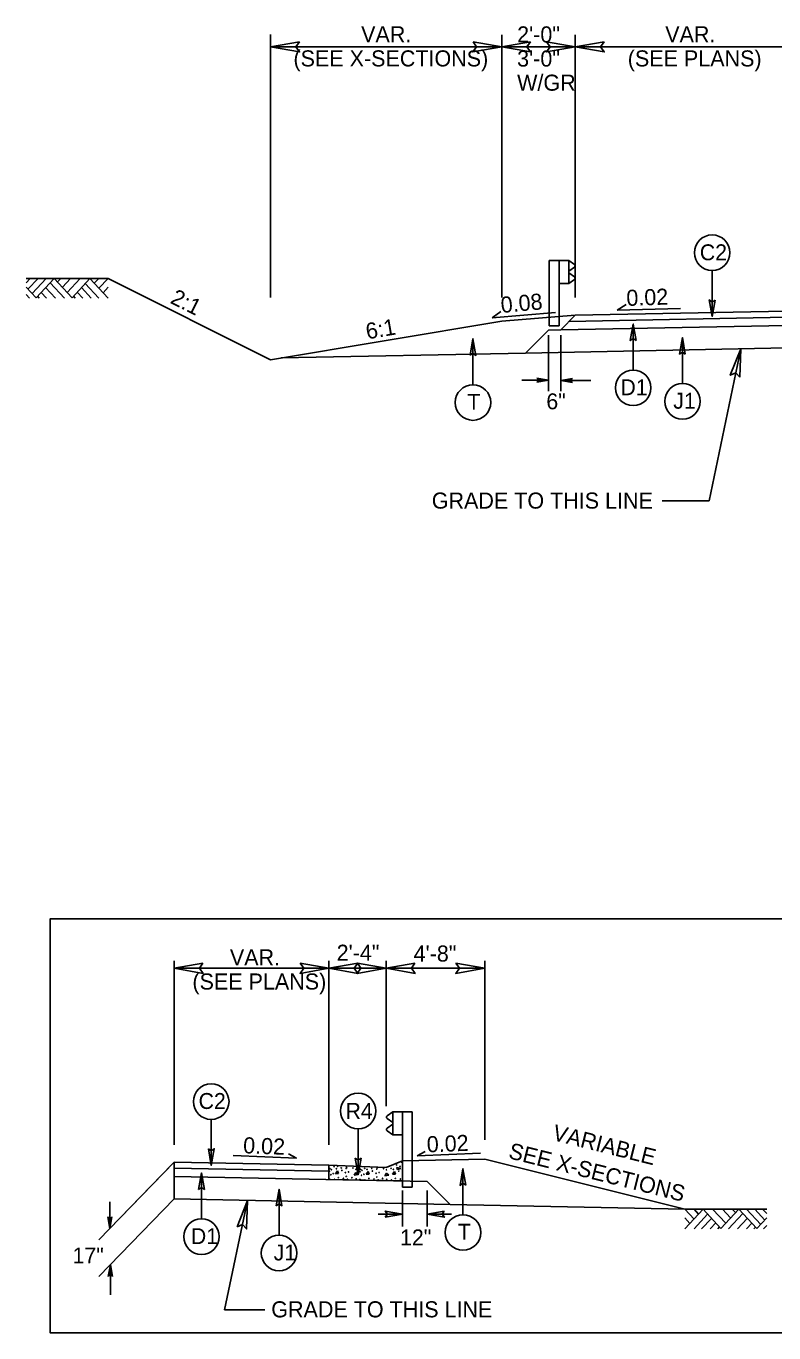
# Model space of a CAD drawing. Extents: x 1901582 to 1902252, y 193723 to 194156.
# Drawn here: x 1901984 to 1902014.5, y 193874.8 to 193928 of the extents above; entities that cross this region are included whole.
import ezdxf

# ---------------------------------------------------------------- set-up
doc = ezdxf.new("R2010")
doc.units = 0
for name, color, linetype in [('Default', 7, 'Continuous'), ('Old_Level_1', 7, 'Continuous'), ('Old_Level_11', 7, 'Continuous'), ('Old_Level_2', 7, 'Continuous'), ('Old_Level_20', 7, 'Continuous'), ('Prop Dimension', 7, 'Continuous'), ('Prop Dimension Text', 7, 'Continuous'), ('Typical Curb CELL', 7, 'Continuous'), ('Typical Guardrail CELL', 7, 'Continuous'), ('Typical Pavement Slope Information CELL', 7, 'Continuous'), ('Typical Slope Point Local CELL', 7, 'Continuous'), ('Typical Terminator CELL', 7, 'Continuous')]:
    doc.layers.add(name, color=color, linetype=linetype)

# ---------------------------------------------------------------- blocks, each defined once
blk = doc.blocks.new('TERMINATOR')
at = {"layer": 'Typical Terminator CELL'}
blk.add_lwpolyline([(-0.469, 0.081), (0, 0), (-0.471, -0.083), (-0.411, 0)], close=True, dxfattribs=at)

msp = doc.modelspace()

# ---------------------------------------------------------------- linework, layer by layer
at = {"layer": 'Default'}
for p, q in [((1901999.372, 193879.106), (1901999.372, 193880.576)), ((1902000.372, 193879.106), (1902000.372, 193880.576)), ((1901999.372, 193879.606), (1901998.372, 193879.606)), ((1902001.372, 193879.606), (1902000.372, 193879.606))]:
    msp.add_line(p, q, dxfattribs=at)
at = {"layer": 'Old_Level_1'}
for p, q in [((1901993.993, 193914.448), (1901987.363, 193917.763)), ((1902006.418, 193916.259), (1902003.418, 193916.019)), ((1902005.755, 193916.498), (1902005.755, 193915.826)), ((1902006.418, 193916.259), (1902005.823, 193915.664)), ((1902016.418, 193916.209), (1902006.163, 193916.004)), ((1902016.418, 193916.459), (1902006.418, 193916.259)), ((1902003.418, 193916.019), (1901993.993, 193914.448)), ((1902005.323, 193915.654), (1902004.387, 193914.718)), ((1902005.823, 193915.664), (1902005.323, 193915.654)), ((1902016.418, 193915.876), (1902005.823, 193915.664)), ((1902004.387, 193914.718), (1901994.417, 193914.519)), ((1902016.418, 193914.959), (1902004.387, 193914.718)), ((1902013.173, 193914.894), (1902011.876, 193908.695)), ((1902004.234, 193913.615), (1902005.323, 193913.615)), ((1902005.323, 193913.615), (1902004.846, 193913.699)), ((1902005.323, 193913.615), (1902004.846, 193913.531)), ((1902005.323, 193913.615), (1902004.855, 193913.688)), ((1902004.855, 193913.542), (1902005.323, 193913.615)), ((1902004.864, 193913.676), (1902005.323, 193913.615)), ((1902005.323, 193913.615), (1902004.864, 193913.556)), ((1902005.323, 193913.615), (1902004.872, 193913.664)), ((1902004.872, 193913.568), (1902005.323, 193913.615)), ((1902004.881, 193913.651), (1902005.323, 193913.615)), ((1902005.323, 193913.615), (1902004.881, 193913.58)), ((1902005.323, 193913.615), (1902004.89, 193913.639)), ((1902004.89, 193913.591), (1902005.323, 193913.615)), ((1902004.899, 193913.627), (1902005.323, 193913.615)), ((1902005.323, 193913.615), (1902004.899, 193913.603)), ((1902004.908, 193913.615), (1902005.323, 193913.615)), ((1902005.823, 193913.599), (1902006.3, 193913.683)), ((1902006.291, 193913.671), (1902005.823, 193913.599)), ((1902005.823, 193913.599), (1902006.282, 193913.659)), ((1902006.273, 193913.647), (1902005.823, 193913.599)), ((1902005.823, 193913.599), (1902006.264, 193913.635)), ((1902006.256, 193913.623), (1902005.823, 193913.599)), ((1902005.823, 193913.599), (1902006.247, 193913.611)), ((1902005.823, 193913.599), (1902006.3, 193913.514)), ((1902006.247, 193913.587), (1902005.823, 193913.599)), ((1902005.823, 193913.599), (1902006.256, 193913.575)), ((1902006.264, 193913.563), (1902005.823, 193913.599)), ((1902005.823, 193913.599), (1902006.273, 193913.551)), ((1902006.282, 193913.539), (1902005.823, 193913.599)), ((1902005.823, 193913.599), (1902006.291, 193913.526)), ((1902005.823, 193913.599), (1902007.048, 193913.599)), ((1902009.967, 193908.695), (1902011.876, 193908.695)), ((1901990.056, 193882.44), (1901990.057, 193889.934)), ((1901996.372, 193882.44), (1901996.372, 193889.934)), ((1901998.706, 193884.016), (1901998.706, 193889.934)), ((1902002.723, 193882.639), (1902002.723, 193889.934)), ((1901990.057, 193889.634), (1901996.372, 193889.634)), ((1901998.706, 193889.634), (1901996.372, 193889.634)), ((1902001.706, 193889.634), (1901998.706, 193889.634)), ((1901998.706, 193889.634), (1902002.723, 193889.634)), ((1901992.464, 193881.992), (1901995.05, 193881.89)), ((1901995.05, 193881.89), (1901994.72, 193882.064)), ((1901999.967, 193881.991), (1902000.297, 193882.164)), ((1902002.553, 193882.092), (1901999.967, 193881.991)), ((1901989.972, 193881.642), (1901986.988, 193878.559)), ((1901990.057, 193881.729), (1901986.989, 193878.559)), ((1901990.056, 193881.729), (1901996.372, 193881.603)), ((1901990.056, 193881.729), (1901990.056, 193880.229)), ((1901990.056, 193881.479), (1901996.372, 193881.353)), ((1901990.056, 193881.479), (1901996.367, 193881.353)), ((1902002.723, 193881.853), (1901999.372, 193881.786)), ((1902002.723, 193881.853), (1902010.886, 193879.812)), ((1901990.056, 193881.146), (1902000.372, 193880.939)), ((1902000.372, 193880.939), (1902001.308, 193880.004)), ((1901990.059, 193880.229), (1901986.99, 193877.059)), ((1901987.437, 193880.111), (1901987.437, 193879.023)), ((1901987.438, 193880.111), (1901987.438, 193879.023)), ((1901990.059, 193880.229), (1902001.308, 193880.004)), ((1901993.048, 193880.169), (1901992.114, 193875.705)), ((1902001.308, 193880.004), (1902010.886, 193879.812)), ((1901987.437, 193879.023), (1901987.353, 193879.5)), ((1901987.438, 193879.023), (1901987.353, 193879.5)), ((1901987.437, 193879.023), (1901987.365, 193879.491)), ((1901987.438, 193879.023), (1901987.365, 193879.491)), ((1901987.377, 193879.482), (1901987.437, 193879.023)), ((1901987.377, 193879.482), (1901987.438, 193879.023)), ((1901987.437, 193879.023), (1901987.389, 193879.474)), ((1901987.438, 193879.023), (1901987.389, 193879.474)), ((1901987.401, 193879.465), (1901987.437, 193879.023)), ((1901987.402, 193879.465), (1901987.438, 193879.023)), ((1901987.437, 193879.023), (1901987.413, 193879.456)), ((1901987.438, 193879.023), (1901987.414, 193879.456)), ((1901987.425, 193879.447), (1901987.437, 193879.023)), ((1901987.426, 193879.447), (1901987.438, 193879.023)), ((1901987.437, 193879.023), (1901987.522, 193879.5)), ((1901987.51, 193879.491), (1901987.437, 193879.023)), ((1901987.437, 193879.023), (1901987.497, 193879.482)), ((1901987.485, 193879.474), (1901987.437, 193879.023)), ((1901987.437, 193879.023), (1901987.473, 193879.465)), ((1901987.461, 193879.456), (1901987.437, 193879.023)), ((1901987.437, 193879.023), (1901987.449, 193879.447)), ((1901987.437, 193879.438), (1901987.437, 193879.023)), ((1901987.438, 193879.023), (1901987.522, 193879.5)), ((1901987.51, 193879.491), (1901987.438, 193879.023)), ((1901987.438, 193879.023), (1901987.497, 193879.482)), ((1901987.485, 193879.474), (1901987.438, 193879.023)), ((1901987.438, 193879.023), (1901987.473, 193879.465)), ((1901987.461, 193879.456), (1901987.438, 193879.023)), ((1901987.438, 193879.023), (1901987.449, 193879.447)), ((1901987.438, 193879.438), (1901987.438, 193879.023)), ((1901987.456, 193877.54), (1901987.372, 193877.063)), ((1901987.384, 193877.072), (1901987.456, 193877.54)), ((1901987.456, 193877.54), (1901987.396, 193877.081)), ((1901987.408, 193877.09), (1901987.456, 193877.54)), ((1901987.456, 193877.54), (1901987.42, 193877.098)), ((1901987.432, 193877.107), (1901987.456, 193877.54)), ((1901987.456, 193877.54), (1901987.444, 193877.116)), ((1901987.456, 193877.54), (1901987.541, 193877.063)), ((1901987.468, 193877.116), (1901987.456, 193877.54)), ((1901987.456, 193877.54), (1901987.48, 193877.107)), ((1901987.492, 193877.098), (1901987.456, 193877.54)), ((1901987.456, 193877.54), (1901987.504, 193877.09)), ((1901987.516, 193877.081), (1901987.456, 193877.54)), ((1901987.456, 193877.54), (1901987.529, 193877.072)), ((1901987.456, 193877.54), (1901987.456, 193876.315)), ((1901993.75, 193875.705), (1901992.114, 193875.705))]:
    msp.add_line(p, q, dxfattribs=at)
for points in [[(1901987.363, 193917.763), (1901984.021, 193917.763)], [(1902010.886, 193879.812), (1902014.228, 193879.812)]]:
    msp.add_lwpolyline(points, dxfattribs=at)
at = {"layer": 'Old_Level_11'}
for p, q in [((1901984.191, 193917.763), (1901984.021, 193917.58)), ((1901984.511, 193917.763), (1901984.097, 193917.319)), ((1901984.844, 193917.763), (1901984.264, 193917.14)), ((1901985.166, 193917.762), (1901984.425, 193916.966)), ((1901985.897, 193916.976), (1901985.166, 193917.762)), ((1901985.43, 193917.763), (1901985.297, 193917.62)), ((1901985.832, 193917.763), (1901985.499, 193917.404)), ((1901986.23, 193917.763), (1901985.697, 193917.19)), ((1901986.621, 193917.755), (1901985.897, 193916.976)), ((1901987.363, 193916.958), (1901986.621, 193917.755)), ((1901986.988, 193917.763), (1901986.801, 193917.562)), ((1901987.363, 193917.763), (1901986.988, 193917.36)), ((1902012.002, 193918.083), (1902012.002, 193916.209)), ((1901984.425, 193916.966), (1901984.021, 193917.401)), ((1901984.155, 193916.958), (1901984.021, 193917.101)), ((1901984.851, 193916.958), (1901984.634, 193917.191)), ((1901985.217, 193916.958), (1901984.817, 193917.387)), ((1901985.587, 193916.958), (1901985.001, 193917.586)), ((1901986.333, 193916.958), (1901986.106, 193917.201)), ((1901986.68, 193916.958), (1901986.279, 193917.387)), ((1901986.989, 193916.958), (1901986.435, 193917.554)), ((1901987.363, 193917.401), (1901987.157, 193917.179)), ((1901984.556, 193916.958), (1901984.487, 193917.032)), ((1901986.022, 193916.958), (1901985.951, 193917.034)), ((1902008.78, 193914.026), (1902008.78, 193915.901)), ((1902002.243, 193913.424), (1902002.243, 193915.299)), ((1902010.789, 193913.477), (1902010.789, 193915.351)), ((1901991.57, 193883.47), (1901991.57, 193881.596)), ((1901997.561, 193883.087), (1901997.561, 193881.213)), ((1902001.837, 193879.582), (1902001.837, 193881.457)), ((1901991.172, 193879.414), (1901991.172, 193881.289)), ((1901994.336, 193878.747), (1901994.336, 193880.621)), ((1902010.886, 193879.812), (1902011.261, 193879.409)), ((1902010.886, 193879.007), (1902011.628, 193879.804)), ((1902011.261, 193879.812), (1902011.448, 193879.611)), ((1902011.628, 193879.804), (1902012.352, 193879.025)), ((1902012.019, 193879.812), (1902012.552, 193879.239)), ((1902012.352, 193879.025), (1902013.083, 193879.811)), ((1902012.417, 193879.812), (1902012.75, 193879.453)), ((1902012.819, 193879.812), (1902012.952, 193879.669)), ((1902013.083, 193879.811), (1902013.824, 193879.015)), ((1902013.405, 193879.812), (1902013.985, 193879.189)), ((1902013.738, 193879.812), (1902014.152, 193879.368)), ((1902014.058, 193879.812), (1902014.228, 193879.629)), ((1902010.886, 193879.45), (1902011.092, 193879.228)), ((1902011.26, 193879.007), (1902011.814, 193879.603)), ((1902011.569, 193879.007), (1902011.97, 193879.436)), ((1902012.662, 193879.007), (1902013.248, 193879.635)), ((1902013.032, 193879.007), (1902013.432, 193879.436)), ((1902013.824, 193879.015), (1902014.228, 193879.45)), ((1902011.916, 193879.007), (1902012.143, 193879.25)), ((1902012.227, 193879.007), (1902012.298, 193879.083)), ((1902013.398, 193879.007), (1902013.615, 193879.24)), ((1902013.693, 193879.007), (1902013.762, 193879.081)), ((1902014.094, 193879.007), (1902014.228, 193879.15))]:
    msp.add_line(p, q, dxfattribs=at)
for points in [[(1902012.118, 193916.881), (1902012.002, 193916.209), (1902011.883, 193916.884), (1902012.002, 193916.799)], [(1902008.896, 193915.229), (1902008.78, 193915.901), (1902008.661, 193915.225), (1902008.78, 193915.311)], [(1902002.127, 193914.627), (1902002.243, 193915.299), (1902002.362, 193914.623), (1902002.243, 193914.709)], [(1902010.904, 193914.679), (1902010.789, 193915.351), (1902010.669, 193914.676), (1902010.789, 193914.761)], [(1902015.245, 193891.651), (1901985.005, 193891.651), (1901985.005, 193874.766), (1902015.245, 193874.766)], [(1901991.455, 193882.268), (1901991.57, 193881.596), (1901991.69, 193882.271), (1901991.57, 193882.186)], [(1901997.445, 193881.885), (1901997.561, 193881.213), (1901997.68, 193881.888), (1901997.561, 193881.803)], [(1902001.953, 193880.785), (1902001.837, 193881.457), (1902001.718, 193880.781), (1902001.837, 193880.867)], [(1901991.057, 193880.617), (1901991.172, 193881.289), (1901991.292, 193880.613), (1901991.172, 193880.699)], [(1901994.221, 193879.949), (1901994.336, 193880.621), (1901994.456, 193879.946), (1901994.336, 193880.031)]]:
    msp.add_lwpolyline(points, close=True, dxfattribs=at)
for centre in [(1902012.002, 193918.809), (1902008.78, 193913.301), (1902002.243, 193912.699), (1902010.789, 193912.751), (1901991.57, 193884.196), (1901997.561, 193883.813), (1901991.172, 193878.689), (1902001.837, 193878.857), (1901994.336, 193878.021)]:
    msp.add_circle(centre, 0.725, dxfattribs=at)
at = {"layer": 'Prop Dimension'}
for p, q in [((1901993.993, 193916.988), (1901993.993, 193927.706)), ((1902003.418, 193917.404), (1902003.418, 193927.699)), ((1902003.418, 193916.988), (1902003.418, 193927.693)), ((1902006.418, 193916.988), (1902006.418, 193927.693)), ((1901993.993, 193927.206), (1902003.418, 193927.206)), ((1902003.418, 193927.206), (1902006.418, 193927.206)), ((1902006.418, 193927.199), (1902016.418, 193927.199)), ((1902005.323, 193913.161), (1902005.323, 193915.454)), ((1902005.823, 193913.161), (1902005.823, 193915.454))]:
    msp.add_line(p, q, dxfattribs=at)
at = {"layer": 'Typical Curb CELL'}
for p, q in [((1901996.372, 193881.603), (1901996.372, 193881.019)), ((1901996.372, 193881.603), (1901998.706, 193881.509)), ((1901998.706, 193881.509), (1901999.372, 193881.786)), ((1901999.145, 193881.515), (1901999.16, 193881.424)), ((1901999.299, 193881.467), (1901999.145, 193881.515)), ((1901999.16, 193881.424), (1901999.299, 193881.467)), ((1901999.372, 193881.786), (1901999.372, 193880.959)), ((1901999.372, 193880.963), (1901996.372, 193881.023)), ((1901996.637, 193881.257), (1901996.726, 193881.375)), ((1901996.758, 193881.261), (1901996.637, 193881.257)), ((1901996.726, 193881.375), (1901996.758, 193881.261)), ((1901997.402, 193881.191), (1901997.466, 193881.304)), ((1901997.568, 193881.227), (1901997.402, 193881.191)), ((1901997.466, 193881.304), (1901997.568, 193881.227)), ((1901997.887, 193881.232), (1901997.975, 193881.35)), ((1901998.007, 193881.236), (1901997.887, 193881.232)), ((1901997.975, 193881.35), (1901998.007, 193881.236)), ((1901998.65, 193881.166), (1901998.715, 193881.279)), ((1901998.817, 193881.202), (1901998.65, 193881.166)), ((1901998.715, 193881.279), (1901998.817, 193881.202)), ((1901998.962, 193881.232), (1901999.05, 193881.35)), ((1901999.082, 193881.236), (1901998.962, 193881.232)), ((1901999.05, 193881.35), (1901999.082, 193881.236))]:
    msp.add_line(p, q, dxfattribs=at)
for centre in [(1901996.415, 193881.456), (1901996.47, 193881.421), (1901996.581, 193881.543), (1901996.676, 193881.456), (1901996.724, 193881.557), (1901996.871, 193881.491), (1901997.076, 193881.471), (1901997.094, 193881.521), (1901997.35, 193881.488), (1901997.469, 193881.435), (1901997.663, 193881.431), (1901997.719, 193881.396), (1901997.829, 193881.476), (1901997.925, 193881.431), (1901998.12, 193881.467), (1901998.325, 193881.446), (1901998.343, 193881.496), (1901998.599, 193881.463), (1901998.718, 193881.41), (1901998.904, 193881.476), (1901999, 193881.431), (1901999.133, 193881.61), (1901999.272, 193881.553), (1901999.327, 193881.734), (1901996.384, 193881.051), (1901996.396, 193881.359), (1901996.45, 193881.215), (1901996.547, 193881.259), (1901996.593, 193881.024), (1901996.754, 193881.089), (1901996.898, 193881.389), (1901996.959, 193881.062), (1901997.044, 193881.301), (1901997.075, 193881.146), (1901997.13, 193881.03), (1901997.17, 193881.327), (1901997.308, 193881.09), (1901997.479, 193881.046), (1901997.632, 193881.026), (1901997.644, 193881.334), (1901997.698, 193881.19), (1901997.796, 193881.234), (1901997.842, 193880.999), (1901998.003, 193881.064), (1901998.146, 193881.364), (1901998.208, 193881.037), (1901998.293, 193881.276), (1901998.324, 193881.121), (1901998.379, 193881.006), (1901998.419, 193881.302), (1901998.557, 193881.065), (1901998.727, 193881.021), (1901998.917, 193880.999), (1901999.079, 193881.064), (1901999.222, 193881.364), (1901999.284, 193881.037)]:
    msp.add_circle(centre, 0.00802, dxfattribs=at)
at = {"layer": 'Typical Guardrail CELL'}
for p, q in [((1902005.755, 193918.487), (1902005.358, 193918.487)), ((1902005.358, 193918.487), (1902005.358, 193915.826)), ((1902005.755, 193918.487), (1902005.755, 193916.498)), ((1902005.755, 193918.487), (1902006.153, 193918.487)), ((1902006.153, 193918.487), (1902006.153, 193917.559)), ((1902006.153, 193918.487), (1902006.385, 193918.325)), ((1902006.153, 193918.06), (1902006.385, 193918.223)), ((1902006.153, 193918.023), (1902006.153, 193918.06)), ((1902006.153, 193918.023), (1902006.153, 193917.986)), ((1902006.153, 193917.986), (1902006.385, 193917.823)), ((1902006.153, 193917.559), (1902006.385, 193917.721)), ((1902005.755, 193917.559), (1902006.153, 193917.559)), ((1902005.755, 193915.826), (1902005.358, 193915.826)), ((1901998.974, 193883.775), (1901998.743, 193883.612)), ((1901999.372, 193883.775), (1901998.974, 193883.775)), ((1901998.974, 193883.775), (1901998.974, 193882.847)), ((1901999.372, 193883.775), (1901999.372, 193881.786)), ((1901999.372, 193883.775), (1901999.77, 193883.775)), ((1901999.77, 193883.775), (1901999.77, 193881.794)), ((1901998.974, 193883.348), (1901998.743, 193883.51)), ((1901998.974, 193883.273), (1901998.743, 193883.111)), ((1901998.974, 193882.847), (1901998.743, 193883.009)), ((1901998.974, 193883.311), (1901998.974, 193883.348)), ((1901998.974, 193883.311), (1901998.974, 193883.273)), ((1901999.372, 193882.847), (1901998.974, 193882.847)), ((1901999.372, 193881.786), (1901999.372, 193880.709)), ((1901999.77, 193881.794), (1901999.77, 193880.701)), ((1901999.372, 193880.701), (1901999.77, 193880.701))]:
    msp.add_line(p, q, dxfattribs=at)
for centre, start, end in [((1902006.349, 193918.274), 304.9888, 54.997), ((1902006.349, 193917.772), 304.9634, 54.9941), ((1901998.778, 193883.561), 125.003, 235.0112), ((1901998.778, 193883.06), 125.0059, 235.0366)]:
    msp.add_arc(centre, 0.0621, start, end, dxfattribs=at)
at = {"layer": 'Typical Pavement Slope Information CELL'}
for p, q in [((1902008.12, 193916.468), (1902008.495, 193916.697)), ((1902003.024, 193916.161), (1902003.386, 193916.41)), ((1902003.024, 193916.161), (1902005.605, 193916.367)), ((1902008.12, 193916.468), (1902010.709, 193916.53))]:
    msp.add_line(p, q, dxfattribs=at)
at = {"layer": 'Typical Terminator CELL'}
for points in [[(1901995.165, 193927.407), (1901993.993, 193927.206), (1901995.171, 193926.997), (1901995.022, 193927.206)], [(1902002.246, 193927.407), (1902003.418, 193927.206), (1902002.239, 193926.997), (1902002.389, 193927.206)], [(1902004.589, 193927.407), (1902003.418, 193927.206), (1902004.596, 193926.997), (1902004.446, 193927.206)], [(1902005.246, 193927.407), (1902006.418, 193927.206), (1902005.239, 193926.997), (1902005.389, 193927.206)], [(1902007.589, 193927.407), (1902006.418, 193927.206), (1902007.596, 193926.997), (1902007.446, 193927.206)], [(1902013.132, 193913.738), (1902013.173, 193914.894), (1902012.74, 193913.814), (1902012.968, 193913.915)], [(1901991.228, 193889.836), (1901990.057, 193889.634), (1901991.235, 193889.426), (1901991.085, 193889.634)], [(1901995.201, 193889.836), (1901996.372, 193889.634), (1901995.194, 193889.426), (1901995.344, 193889.634)], [(1901997.544, 193889.836), (1901996.372, 193889.634), (1901997.551, 193889.426), (1901997.401, 193889.634)], [(1901997.534, 193889.836), (1901998.706, 193889.634), (1901997.527, 193889.426), (1901997.677, 193889.634)], [(1901999.877, 193889.836), (1901998.706, 193889.634), (1901999.884, 193889.426), (1901999.734, 193889.634)], [(1902001.551, 193889.836), (1902002.723, 193889.634), (1902001.544, 193889.426), (1902001.694, 193889.634)], [(1901992.623, 193879.094), (1901993.048, 193880.169), (1901993.012, 193879.006), (1901992.843, 193879.19)]]:
    msp.add_lwpolyline(points, close=True, dxfattribs=at)

# ---------------------------------------------------------------- block references
at = {"layer": 'Old_Level_1', "xscale": 1.5, "yscale": -1.5}
msp.add_blockref('TERMINATOR', (1901999.372, 193879.606), dxfattribs=at)
at = {"layer": 'Old_Level_1', "xscale": 1.5, "yscale": -1.5, "rotation": -180}
msp.add_blockref('TERMINATOR', (1902000.372, 193879.606), dxfattribs=at)

# ---------------------------------------------------------------- texts
at = {"layer": 'Old_Level_1'}
for s, p in [('VAR.', (1901997.683, 193927.389)), ('VAR.', (1902010.086, 193927.388)), ('(SEE X-SECTIONS)', (1901994.923, 193926.405)), ('(SEE PLANS)', (1902008.557, 193926.404)), ('GRADE TO THIS LINE', (1902000.565, 193908.375)), ('2\'-4"', (1901996.685, 193889.938)), ('4\'-8"', (1901999.824, 193889.906)), ('VAR.', (1901992.331, 193889.749)), ('(SEE PLANS)', (1901990.802, 193888.765)), ('GRADE TO THIS LINE', (1901994.019, 193875.398))]:
    msp.add_text(s, height=0.656, dxfattribs=at).set_placement(p)
for s, p in [('VARIABLE', (1902005.447, 193882.637)), ('SEE X-SECTIONS', (1902003.656, 193881.894))]:
    msp.add_text(s, height=0.656, rotation=345.9638, dxfattribs=at).set_placement(p)
at = {"layer": 'Old_Level_2'}
for s, rotation, p in [('0.08', 5.1891, (1902003.406, 193916.351)), ('0.02', 1.9721, (1902008.512, 193916.637)), ('0.02', 357.7461, (1901992.862, 193882.093)), ('0.02', 2.2539, (1902000.373, 193882.124))]:
    msp.add_text(s, height=0.656, rotation=rotation, dxfattribs=at).set_placement(p)
at = {"layer": 'Old_Level_20'}
for s, height, p in [('C2', 0.6491, (1902011.496, 193918.502)), ('D1', 0.6491, (1902008.259, 193912.998)), ('T', 0.649, (1902002.015, 193912.406)), ('6"', 0.6491, (1902005.238, 193912.425)), ('J1', 0.6491, (1902010.414, 193912.448)), ('C2', 0.6491, (1901991.054, 193883.896)), ('R4', 0.6491, (1901997.045, 193883.493)), ('D1', 0.6491, (1901990.739, 193878.386)), ('12"', 0.6491, (1901999.273, 193878.334)), ('T', 0.649, (1902001.626, 193878.564)), ('17"', 0.6491, (1901985.915, 193877.597)), ('J1', 0.6491, (1901994.118, 193877.718))]:
    msp.add_text(s, height=height, dxfattribs=at).set_placement(p)
at = {"layer": 'Prop Dimension Text'}
for s, p in [('2\'-0"', (1902004.046, 193927.383)), ('3\'-0"', (1902004.046, 193926.399)), ('W/GR', (1902004.046, 193925.415))]:
    msp.add_text(s, height=0.656, dxfattribs=at).set_placement(p)
at = {"layer": 'Typical Slope Point Local CELL'}
for s, rotation, p in [('2:1', 333.4349, (1901989.859, 193916.773)), ('6:1', 9.8144, (1901997.932, 193915.273))]:
    msp.add_text(s, height=0.656, rotation=rotation, dxfattribs=at).set_placement(p)

doc.saveas('drawing.dxf')
